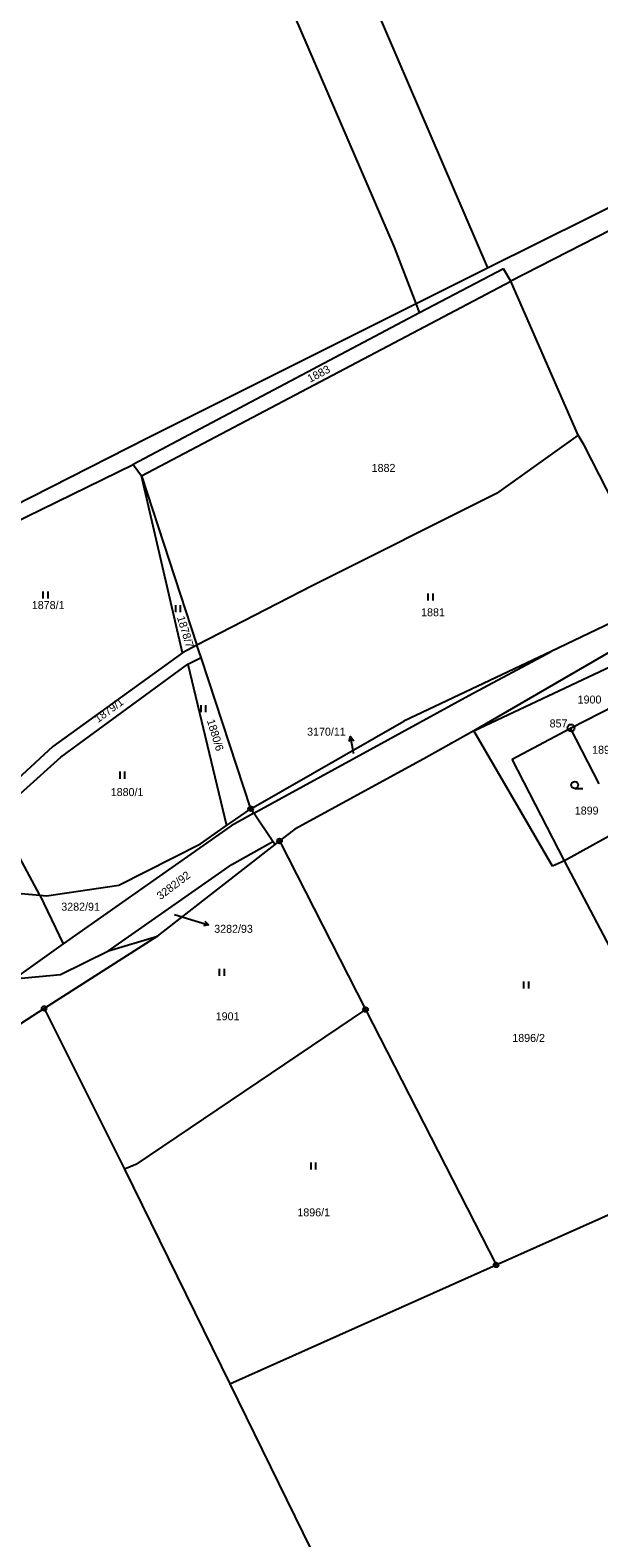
# Model space of a CAD drawing. Extents: x -736345 to -729997, y -1130177 to -1122501.
# Drawn here: x -731794.6 to -731673.6, y -1127368 to -1127046.9 of the extents above; entities that cross this region are included whole.
import ezdxf

# ---------------------------------------------------------------- set-up
doc = ezdxf.new("R2010")
doc.units = 0
for name, color, linetype in [('Vrstva 1', 7, 'Continuous'), ('Vrstva 16', 7, 'Continuous'), ('Vrstva 17', 7, 'Continuous'), ('Vrstva 18', 7, 'Continuous'), ('Vrstva 19', 7, 'Continuous'), ('Vrstva 25', 7, 'Continuous')]:
    doc.layers.add(name, color=color, linetype=linetype)

msp = doc.modelspace()

# ---------------------------------------------------------------- linework, layer by layer
at = {"layer": 'Vrstva 1'}
for points in [[(-731733.3, -1127013.82), (-731697.29, -1127097.48)], [(-731717.09, -1127093.09), (-731749.6, -1127017.72)], [(-731697.29, -1127097.48), (-731643.17, -1127070.58)], [(-731640.6, -1127073.84), (-731692.36, -1127100.37)], [(-731712.52, -1127105.11), (-731717.09, -1127093.09)], [(-731712.52, -1127105.11), (-731697.29, -1127097.48)], [(-731693.92, -1127097.69), (-731711.75, -1127107.12)], [(-731692.36, -1127100.37), (-731693.92, -1127097.69)], [(-731770.96, -1127141.83), (-731692.36, -1127100.37)], [(-731677.98, -1127133.12), (-731692.36, -1127100.37)], [(-731769.68, -1127133.74), (-731712.52, -1127105.11)], [(-731711.87, -1127106.82), (-731712.52, -1127105.11)], [(-731711.75, -1127107.12), (-731772.7, -1127139.39)], [(-731711.75, -1127107.12), (-731711.87, -1127106.82)], [(-731819.08, -1127158.84), (-731769.68, -1127133.74)], [(-731677.98, -1127133.12), (-731695.38, -1127145.57)], [(-731676.7, -1127135.31), (-731677.98, -1127133.12)], [(-731660.61, -1127166.83), (-731676.7, -1127135.31)], [(-731811.79, -1127158.47), (-731772.7, -1127139.39)], [(-731772.7, -1127139.39), (-731770.96, -1127141.83)], [(-731770.96, -1127141.83), (-731759.14, -1127177.89)], [(-731762.25, -1127179.49), (-731770.96, -1127141.83)], [(-731695.38, -1127145.57), (-731734.6, -1127165.22)], [(-731734.6, -1127165.22), (-731759.14, -1127177.89)], [(-731662.82, -1127169.25), (-731683.78, -1127179.21)], [(-731657.18, -1127171.13), (-731700.24, -1127196.17)], [(-731700.24, -1127196.17), (-731658.9, -1127176.65)], [(-731762.25, -1127179.49), (-731789.82, -1127199.49)], [(-731759.14, -1127177.89), (-731762.25, -1127179.49)], [(-731758.28, -1127180.49), (-731759.14, -1127177.89)], [(-731683.78, -1127179.21), (-731715.11, -1127194.09)], [(-731701.28, -1127188.58), (-731683.78, -1127179.21)], [(-731788.14, -1127201.78), (-731761.06, -1127181.9)], [(-731761.06, -1127181.9), (-731758.28, -1127180.49)], [(-731761.06, -1127181.9), (-731752.83, -1127216.29)], [(-731747.71, -1127212.74), (-731758.28, -1127180.49)], [(-731747.06, -1127213.7), (-731701.28, -1127188.58)], [(-731679.62, -1127195.56), (-731667.04, -1127189.14)], [(-731747.71, -1127212.74), (-731715.11, -1127194.09)], [(-731692.03, -1127202.16), (-731679.62, -1127195.56)], [(-731673.55, -1127207.45), (-731679.62, -1127195.56)], [(-731700.24, -1127196.17), (-731710.87, -1127202.07)], [(-731690.16, -1127213.46), (-731700.24, -1127196.17)], [(-731789.82, -1127199.49), (-731803.08, -1127211.66)], [(-731801.81, -1127214.03), (-731788.14, -1127201.78)], [(-731710.87, -1127202.07), (-731738.3, -1127217.05)], [(-731680.92, -1127223.83), (-731692.03, -1127202.16)], [(-731792.57, -1127231.16), (-731801.81, -1127214.03)], [(-731752.03, -1127215.74), (-731747.71, -1127212.74)], [(-731747.06, -1127213.7), (-731751.87, -1127216.38)], [(-731747.06, -1127213.7), (-731747.71, -1127212.74)], [(-731742.99, -1127219.68), (-731747.06, -1127213.7)], [(-731683.45, -1127224.96), (-731690.16, -1127213.46)], [(-731662.8, -1127213.83), (-731680.92, -1127223.83)], [(-731751.87, -1127216.38), (-731787.65, -1127241.52)], [(-731758.42, -1127220.18), (-731752.83, -1127216.29)], [(-731752.83, -1127216.29), (-731752.03, -1127215.74)], [(-731738.3, -1127217.05), (-731741.57, -1127219.6)], [(-731775.75, -1127229.03), (-731758.42, -1127220.18)], [(-731767.55, -1127239.84), (-731742.53, -1127220.35)], [(-731751.73, -1127224.58), (-731742.99, -1127219.68)], [(-731742.53, -1127220.35), (-731742.99, -1127219.68)], [(-731742.53, -1127220.35), (-731741.57, -1127219.6)], [(-731741.57, -1127219.6), (-731723.25, -1127255.5)], [(-731777.99, -1127243), (-731751.73, -1127224.58)], [(-731680.92, -1127223.83), (-731683.45, -1127224.96)], [(-731671.17, -1127242.28), (-731680.92, -1127223.83)], [(-731805.36, -1127229.99), (-731792.57, -1127231.16)], [(-731792.57, -1127231.16), (-731787.65, -1127241.52)], [(-731792.57, -1127231.16), (-731791.19, -1127231.29)], [(-731791.19, -1127231.29), (-731775.75, -1127229.03)], [(-731767.55, -1127239.84), (-731791.67, -1127255.26)], [(-731777.99, -1127243), (-731767.55, -1127239.84)], [(-731787.65, -1127241.52), (-731798.07, -1127248.98)], [(-731788.18, -1127248.02), (-731777.99, -1127243)], [(-731798.07, -1127248.98), (-731788.18, -1127248.02)], [(-731791.67, -1127255.26), (-731835.63, -1127283.72)], [(-731791.67, -1127255.26), (-731774.57, -1127289.51)], [(-731723.25, -1127255.5), (-731772.13, -1127288.52)], [(-731723.25, -1127255.5), (-731695.49, -1127309.91)], [(-731772.13, -1127288.52), (-731774.57, -1127289.51)], [(-731695.49, -1127309.91), (-731646.63, -1127288.06)], [(-731774.57, -1127289.51), (-731752.15, -1127335.24)], [(-731752.15, -1127335.24), (-731695.49, -1127309.91)], [(-731752.15, -1127335.24), (-731717.61, -1127405.83)]]:
    msp.add_lwpolyline(points, dxfattribs=at)
at = {"layer": 'Vrstva 16'}
for points in [[(-731725.8, -1127200.99), (-731725.92, -1127200.32)], [(-731763.92, -1127235.28), (-731759.54, -1127236.6)]]:
    msp.add_lwpolyline(points, dxfattribs=at)
at = {"layer": 'Vrstva 25'}
for points in [[(-731791.877, -1127167.965), (-731791.877, -1127166.465)], [(-731790.843, -1127167.965), (-731790.843, -1127166.465)], [(-731709.927, -1127168.375), (-731709.927, -1127166.875)], [(-731708.893, -1127168.375), (-731708.893, -1127166.875)], [(-731763.657, -1127170.865), (-731763.657, -1127169.365)], [(-731762.623, -1127170.865), (-731762.623, -1127169.365)], [(-731758.267, -1127192.155), (-731758.267, -1127190.655)], [(-731757.233, -1127192.155), (-731757.233, -1127190.655)], [(-731726.759, -1127198.438), (-731726.44, -1127197.366), (-731725.775, -1127198.264)], [(-731725.92, -1127200.32), (-731726.44, -1127197.366)], [(-731775.497, -1127206.325), (-731775.497, -1127204.825)], [(-731774.463, -1127206.325), (-731774.463, -1127204.825)], [(-731678.74, -1127208.41), (-731676.99, -1127208.41)], [(-731759.54, -1127236.6), (-731756.669, -1127237.467)], [(-731757.481, -1127236.699), (-731756.669, -1127237.467), (-731757.77, -1127237.656)], [(-731754.347, -1127248.315), (-731754.347, -1127246.815)], [(-731753.313, -1127248.315), (-731753.313, -1127246.815)], [(-731689.567, -1127251.035), (-731689.567, -1127249.535)], [(-731688.533, -1127251.035), (-731688.533, -1127249.535)], [(-731734.867, -1127289.555), (-731734.867, -1127288.055)], [(-731733.833, -1127289.555), (-731733.833, -1127288.055)]]:
    msp.add_lwpolyline(points, dxfattribs=at)
for centre, radius in [((-731679.52, -1127195.51), 0.75), ((-731679.52, -1127195.51), 0.032), ((-731678.74, -1127207.66), 0.75), ((-731747.71, -1127212.74), 0.5), ((-731747.71, -1127212.74), 0.032), ((-731741.57, -1127219.6), 0.5), ((-731741.57, -1127219.6), 0.032), ((-731791.67, -1127255.26), 0.5), ((-731791.67, -1127255.26), 0.032), ((-731723.25, -1127255.5), 0.5), ((-731723.25, -1127255.5), 0.032), ((-731695.49, -1127309.91), 0.5), ((-731695.49, -1127309.91), 0.032)]:
    msp.add_circle(centre, radius, dxfattribs=at)

# ---------------------------------------------------------------- texts
at = {"layer": 'Vrstva 16'}
for s, p in [('3170/11', (-731735.697, -1127197.17)), ('3282/93', (-731755.47, -1127239.16))]:
    msp.add_text(s, height=1.7, dxfattribs=at).set_placement(p)
at = {"layer": 'Vrstva 17'}
msp.add_text('857', height=1.7, dxfattribs=at).set_placement((-731684.09, -1127195.41))
at = {"layer": 'Vrstva 18'}
for s, rotation, p in [('1883', 27.70022, (-731735.076, -1127122.01)), ('1878/7', 287.10228, (-731763.421, -1127171.962)), ('1879/1', 36.50029, (-731780.179, -1127194.491)), ('1880/6', 287.10228, (-731757.061, -1127193.952)), ('3282/92', 37.3003, (-731766.903, -1127232.22))]:
    msp.add_text(s, height=1.7, rotation=rotation, dxfattribs=at).set_placement(p)
for s, height, p in [('1882', 1.7, (-731721.96, -1127140.98)), ('1878/1', 1.7, (-731794.29, -1127170.2)), ('1881', 1.7, (-731711.43, -1127171.73)), ('1900', 1.7, (-731678.12, -1127190.32)), ('3170/11', 0.1, (-731725.6, -1127200.79)), ('1880/1', 1.7, (-731777.49, -1127210.03)), ('1899', 1.7, (-731678.73, -1127213.97)), ('3282/91', 1.7, (-731788.02, -1127234.45)), ('3282/93', 0.1, (-731763.72, -1127235.08)), ('1901', 1.7, (-731755.15, -1127257.79)), ('1896/2', 1.7, (-731692.03, -1127262.4)), ('1896/1', 1.7, (-731737.77, -1127299.56))]:
    msp.add_text(s, height=height, dxfattribs=at).set_placement(p)
at = {"layer": 'Vrstva 19'}
msp.add_text('1898', height=1.7, dxfattribs=at).set_placement((-731675.04, -1127201.02))

doc.saveas('drawing.dxf')
